Omron CX-Programmer project NuevoProyecto (CX-Programmer 9.50)

# PLC NewPLC1: CQM1 CPU21

## Program P1_4 (no task)
Local symbols
B 100.00 BOOL
Etapa_0 10.00 BOOL
Etapa_1 10.01 BOOL
Etapa_2 10.02 BOOL
Etapa_3 10.03 BOOL
FSP 15.00 BOOL
p 0.00 BOOL

### Section Sección1_Programa_principal
; Programa principal (Etapas 0 y 1)

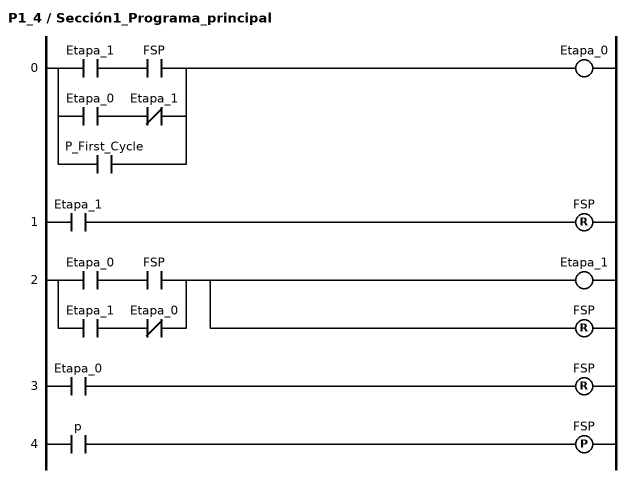
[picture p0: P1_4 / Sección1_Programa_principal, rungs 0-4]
; rung 0
LD Etapa_1
AND FSP
LD Etapa_0
ANDNOT Etapa_1
ORLD
OR P_First_Cycle
OUT Etapa_0
; rung 1
LD Etapa_1
RSET FSP
; rung 2
LD Etapa_0
AND FSP
LD Etapa_1
ANDNOT Etapa_0
ORLD
OUT Etapa_1
RSET FSP
; rung 3
LD Etapa_0
RSET FSP
; rung 4
LD p
DIFU(13) FSP

### Section Sección2_Salida

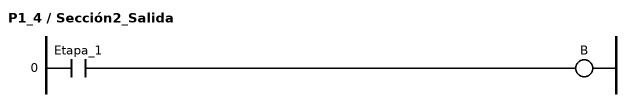
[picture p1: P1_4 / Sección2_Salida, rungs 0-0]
; rung 0
LD Etapa_1
OUT B

### Section Sección3_END
; rung 0
END(01)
